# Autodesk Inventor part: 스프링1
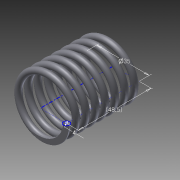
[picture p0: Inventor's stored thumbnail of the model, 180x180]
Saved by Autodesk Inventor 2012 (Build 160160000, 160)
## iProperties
Created: 2014-12
Part Number: 스프링1
Material: 탄소강
Document SubType Name: Modeling
Designer: Owner
Mass: 80.1205 g
Surface Area: 103 cm^2
Volume: 10.1805 cm^3
Density: 7.87 g/cm^3
Author: Owner
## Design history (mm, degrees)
sketch "스케치1"
  geometry: L1 (0, 0)-(17.5, 0); L2 (17.5, 0)-(17.5, 48.5); L3 (17.5, 48.5)-(0, 48.5); L4 (0, 48.5)-(0, 0); C1 r 2 at (17.5, 0)
  constraints: 8 end point, 2 parallel, 1 centre point, 1 coincident, 1 horizontal, 1 perpendicular
  dimensions: "d0" = 4 diameter of C1; "d1" = 35 diameter of L2 L4; "d2" = 48.5 distance of L1.end L2.end (derived)
feature "코일1" pitch "d3" = 10; turns "d5" = 7.5; dims "d4" = 48.5 (= d2), "d6" = 0, angle "d7" = 90 deg, angle "d8" = 90 deg, "d9" = 0, "d10" = 0
sketch "스케치2"
  geometry: L1 (-19.5, 0)-(-15.5, 0) reference; 1 further point
  constraints: 1 horizontal alignment
extrude "돌출1" cut sketch "스케치2" stored distance "d11" = 10; taper "d12" = 0 deg
node "작업 평면1"
sketch "스케치3"
  geometry: L1 (15.5, 0)-(19.5, 0) reference; 1 further point
  constraints: 1 horizontal alignment
extrude "돌출2" cut sketch "스케치3" stored distance "d13" = 10; taper "d14" = 0 deg
node "솔리드1"
node "절단 모서리 투영1"
node "절단 모서리 투영2"
